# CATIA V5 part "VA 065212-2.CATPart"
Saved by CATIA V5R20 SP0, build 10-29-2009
Part number: VA 065212-2
Revision: ANY
Definition: UNKNOWN
Nomenclature: VA 065212-2
Source: Unknown
Bounding box of the stored display mesh (mm): x -3 to 2.853, y 0.1 to 12.1, z -3 to 3
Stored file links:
  C:\Users\Utente\Desktop\IO LAVORO\3D X SITO CF\CUMSA\3D files VA\VA 065212\VA 065212-2.CATPart
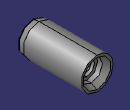
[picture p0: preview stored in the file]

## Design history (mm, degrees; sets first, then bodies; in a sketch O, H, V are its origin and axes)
Body1 "Cortar-Extruir1" (main body)
  Solid1: solid without history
